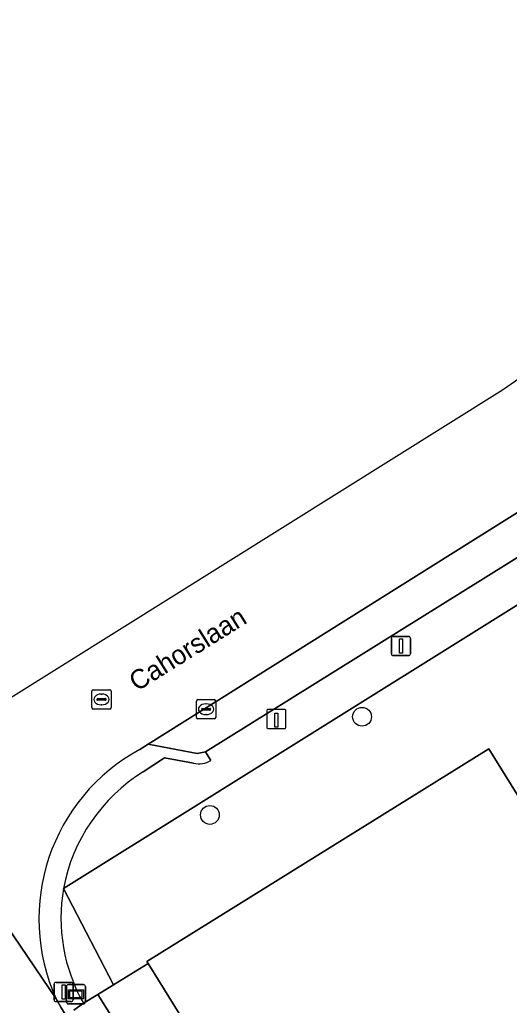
# Model space of a CAD drawing. Extents: x 158455 to 159797, y 387218 to 388672.
# Drawn here: x 158697.3 to 158722.7, y 388005.1 to 388056.4 of the extents above; entities that cross this region are included whole.
import ezdxf

# ---------------------------------------------------------------- set-up
doc = ezdxf.new("R2010")
doc.units = 0
for name, color, linetype in [('IMGEO_Boom', 7, 'Continuous'), ('IMGEO_Erf', 7, 'Continuous'), ('IMGEO_Kolk', 7, 'Continuous'), ('IMGEO_Laadpaal', 7, 'Continuous'), ('IMGEO_Lichtmast', 7, 'Continuous'), ('IMGEO_Openbare_ruimte_label', 7, 'Continuous'), ('IMGEO_Pand', 7, 'Continuous'), ('IMGEO_Parkeervlak_open', 7, 'Continuous'), ('IMGEO_Rijbaan_lokaal_gesloten', 7, 'Continuous'), ('IMGEO_Rioolput', 7, 'Continuous'), ('IMGEO_Voetpad_open', 7, 'Continuous'), ('IMGEO_Wegwijzer', 7, 'Continuous')]:
    doc.layers.add(name, color=color, linetype=linetype)

msp = doc.modelspace()

# ---------------------------------------------------------------- linework, layer by layer
at = {"layer": 'IMGEO_Boom'}
for centre in [(158715.077, 388020.119), (158707.161, 388015.014)]:
    msp.add_circle(centre, 0.489, dxfattribs=at)
at = {"layer": 'IMGEO_Erf'}
msp.add_lwpolyline([(158790.47, 387981.392), (158753.29, 388041.304), (158752.718, 388041.901), (158751.855, 388042.396), (158751.213, 388042.565), (158750.549, 388042.598), (158749.577, 388042.387), (158748.718, 388041.887), (158699.543, 388011.196), (158702.142, 388006.173), (158703.945, 388007.288), (158703.876, 388007.399), (158721.666, 388018.457), (158724.306, 388014.211), (158731.654, 388002.39)], dxfattribs=at)
at = {"layer": 'IMGEO_Kolk'}
for p, q in [((158706.459, 388020.086), (158706.459, 388020.938)), ((158706.534, 388021.012), (158707.386, 388021.012)), ((158707.46, 388020.938), (158707.46, 388020.086)), ((158706.718, 388020.506), (158706.718, 388020.518)), ((158707.156, 388020.469), (158706.758, 388020.469)), ((158706.761, 388020.555), (158707.159, 388020.555)), ((158706.947, 388020.792), (158706.972, 388020.792)), ((158707.202, 388020.518), (158707.202, 388020.506)), ((158707.386, 388020.012), (158706.534, 388020.012)), ((158706.97, 388020.232), (158706.945, 388020.232))]:
    msp.add_line(p, q, dxfattribs=at)
for points in [[(158706.459, 388020.086), (158706.459, 388020.938)], [(158706.534, 388021.012), (158707.386, 388021.012)], [(158707.46, 388020.938), (158707.46, 388020.086)], [(158707.386, 388020.012), (158706.534, 388020.012)]]:
    msp.add_lwpolyline(points, dxfattribs=at)
for centre, radius, start, end in [((158706.536, 388020.936), 0.0765, 91.552, 178.448), ((158706.536, 388020.936), 0.0765, 91.552, 178.448), ((158707.384, 388020.936), 0.0765, 1.552, 88.448), ((158707.384, 388020.936), 0.0765, 1.552, 88.448), ((158706.758, 388020.515), 0.0403, 85.8775, 175.7526), ((158706.755, 388020.505), 0.0366, 178.938, 274.7102), ((158707.159, 388020.512), 0.043, 264.8664, 352.4533), ((158707.163, 388020.517), 0.0386, 1.7309, 96.639), ((158706.536, 388020.088), 0.0765, 181.552, 268.448), ((158706.536, 388020.088), 0.0765, 181.552, 268.448), ((158707.384, 388020.088), 0.0765, 271.552, 358.448), ((158707.384, 388020.088), 0.0765, 271.552, 358.448)]:
    msp.add_arc(centre, radius, start, end, dxfattribs=at)
for centre, major_axis, ratio, start_param, end_param in [((158706.946, 388020.512), (-0.387, 0.002), 0.722429, 4.712389, 7.853982), ((158706.971, 388020.512), (-0.39, 0.002), 0.717154, 1.570796, 4.712389)]:
    msp.add_ellipse(centre, major_axis=major_axis, ratio=ratio, start_param=start_param, end_param=end_param, dxfattribs=at)
at = {"layer": 'IMGEO_Laadpaal'}
for p, q in [((158710.115, 388020.418), (158710.115, 388019.577)), ((158710.115, 388020.418), (158710.115, 388019.577)), ((158711.031, 388020.502), (158710.19, 388020.502)), ((158711.031, 388020.502), (158710.19, 388020.502)), ((158711.115, 388019.586), (158711.115, 388020.427)), ((158711.115, 388019.586), (158711.115, 388020.427)), ((158710.199, 388019.502), (158711.04, 388019.502)), ((158710.199, 388019.502), (158711.04, 388019.502))]:
    msp.add_line(p, q, dxfattribs=at)
msp.add_lwpolyline([(158710.53, 388020.315), (158710.69, 388020.315), (158710.69, 388019.582), (158710.53, 388019.582), (158710.53, 388020.315)], dxfattribs=at)
for centre, start, end in [((158710.193, 388020.424), 92.4484, 184.2845), ((158710.193, 388020.424), 92.4484, 184.2845), ((158711.037, 388020.424), 2.4484, 94.2845), ((158711.037, 388020.424), 2.4484, 94.2845), ((158710.193, 388019.58), 182.4484, 274.2845), ((158710.193, 388019.58), 182.4484, 274.2845), ((158711.037, 388019.58), 272.4484, 4.2845), ((158711.037, 388019.58), 272.4484, 4.2845)]:
    msp.add_arc(centre, 0.0779, start, end, dxfattribs=at)
at = {"layer": 'IMGEO_Lichtmast'}
for p, q in [((158716.603, 388023.398), (158716.603, 388024.198)), ((158716.603, 388024.198), (158716.603, 388023.398)), ((158716.703, 388024.298), (158717.493, 388024.298)), ((158717.493, 388024.298), (158716.703, 388024.298)), ((158717.593, 388024.198), (158717.593, 388023.398)), ((158717.593, 388023.398), (158717.593, 388024.198)), ((158717.493, 388023.298), (158716.703, 388023.298)), ((158716.703, 388023.298), (158717.493, 388023.298)), ((158699.053, 388005.405), (158699.053, 388006.205)), ((158699.053, 388006.205), (158699.053, 388005.405)), ((158699.153, 388006.305), (158699.943, 388006.305)), ((158699.943, 388006.305), (158699.153, 388006.305)), ((158700.043, 388006.205), (158700.043, 388005.405)), ((158700.043, 388005.405), (158700.043, 388006.205)), ((158699.943, 388005.305), (158699.153, 388005.305)), ((158699.153, 388005.305), (158699.943, 388005.305))]:
    msp.add_line(p, q, dxfattribs=at)
for points in [[(158717.023, 388024.173), (158717.173, 388024.173), (158717.173, 388023.423), (158717.023, 388023.423), (158717.023, 388024.173)], [(158699.473, 388006.18), (158699.623, 388006.18), (158699.623, 388005.43), (158699.473, 388005.43), (158699.473, 388006.18)]]:
    msp.add_lwpolyline(points, dxfattribs=at)
for centre, start, end in [((158716.703, 388024.198), 90, 180), ((158716.703, 388024.198), 90, 180), ((158717.493, 388024.198), 0, 90), ((158717.493, 388024.198), 360, 90), ((158716.703, 388023.398), 180, 270), ((158716.703, 388023.398), 180, 270), ((158717.493, 388023.398), 270, 0), ((158717.493, 388023.398), 270, 0), ((158699.153, 388006.205), 90, 180), ((158699.153, 388006.205), 90, 180), ((158699.943, 388006.205), 0, 90), ((158699.943, 388006.205), 360, 90), ((158699.153, 388005.405), 180, 270), ((158699.153, 388005.405), 180, 270), ((158699.943, 388005.405), 270, 0), ((158699.943, 388005.405), 270, 0)]:
    msp.add_arc(centre, 0.1, start, end, dxfattribs=at)
at = {"layer": 'IMGEO_Pand'}
msp.add_lwpolyline([(158703.876, 388007.399), (158703.945, 388007.288), (158706.413, 388003.317), (158708.475, 388000), (158711.147, 387995.701), (158715.986, 387987.917), (158721.39, 387979.223), (158725.756, 387972.2), (158728.643, 387967.556), (158732.89, 387970.196), (158743.067, 387976.522), (158728.473, 388000), (158728.288, 388000.298), (158731.654, 388002.39), (158724.306, 388014.211), (158721.666, 388018.457)], close=True, dxfattribs=at)
at = {"layer": 'IMGEO_Parkeervlak_open'}
msp.add_lwpolyline([(158742.388, 388039.817), (158743.581, 388042.372), (158738.848, 388040.074), (158733.166, 388036.841), (158727.312, 388033.343), (158703.955, 388018.697), (158706.489, 388018.215), (158706.932, 388018.293), (158728.28, 388031.59)], dxfattribs=at)
at = {"layer": 'IMGEO_Rijbaan_lokaal_gesloten'}
for points in [[(158750.198, 388056.37), (158722.39, 388037.107), (158690.997, 388017.476), (158699.164, 388005.446)], [(158703.521, 388018.425), (158703.955, 388018.697), (158727.312, 388033.343), (158733.166, 388036.841), (158738.848, 388040.074), (158743.581, 388042.372), (158743.991, 388042.57), (158746.463, 388043.958), (158747.806, 388044.596)], [(158752.139, 387920.533), (158744.044, 387933.465), (158737.513, 387943.899), (158735.552, 387947.084), (158732.398, 387952.094), (158729.154, 387957.3), (158721.495, 387969.575), (158717.131, 387976.644), (158711.737, 387985.247), (158706.858, 387993.094), (158702.152, 388000.597), (158699.396, 388005.012), (158699.164, 388005.446), (158690.997, 388017.476), (158685.259, 388013.888)]]:
    msp.add_lwpolyline(points, dxfattribs=at)
msp.add_arc((158708.298, 388009.601), 10.034, 118.4264, 204.4602, dxfattribs=at)
at = {"layer": 'IMGEO_Rioolput'}
for p, q in [((158701.019, 388020.593), (158701.019, 388021.445)), ((158701.094, 388021.519), (158701.946, 388021.519)), ((158702.02, 388021.445), (158702.02, 388020.593)), ((158701.278, 388021.013), (158701.278, 388021.025)), ((158701.716, 388020.976), (158701.318, 388020.976)), ((158701.321, 388021.062), (158701.719, 388021.062)), ((158701.507, 388021.299), (158701.532, 388021.299)), ((158701.762, 388021.025), (158701.762, 388021.013)), ((158701.946, 388020.519), (158701.094, 388020.519)), ((158701.53, 388020.739), (158701.505, 388020.739))]:
    msp.add_line(p, q, dxfattribs=at)
for points in [[(158701.019, 388020.593), (158701.019, 388021.445)], [(158701.094, 388021.519), (158701.946, 388021.519)], [(158702.02, 388021.445), (158702.02, 388020.593)], [(158701.946, 388020.519), (158701.094, 388020.519)]]:
    msp.add_lwpolyline(points, dxfattribs=at)
for centre, radius, start, end in [((158701.096, 388021.443), 0.0765, 91.552, 178.448), ((158701.096, 388021.443), 0.0765, 91.552, 178.448), ((158701.944, 388021.443), 0.0765, 1.552, 88.448), ((158701.944, 388021.443), 0.0765, 1.552, 88.448), ((158701.318, 388021.022), 0.0403, 85.8775, 175.7526), ((158701.315, 388021.012), 0.0366, 178.938, 274.7102), ((158701.719, 388021.019), 0.043, 264.8664, 352.4533), ((158701.723, 388021.024), 0.0386, 1.7309, 96.639), ((158701.096, 388020.595), 0.0765, 181.552, 268.448), ((158701.096, 388020.595), 0.0765, 181.552, 268.448), ((158701.944, 388020.595), 0.0765, 271.552, 358.448), ((158701.944, 388020.595), 0.0765, 271.552, 358.448)]:
    msp.add_arc(centre, radius, start, end, dxfattribs=at)
for centre, major_axis, ratio, start_param, end_param in [((158701.506, 388021.019), (-0.387, 0.002), 0.722429, 4.712389, 7.853982), ((158701.531, 388021.019), (-0.39, 0.002), 0.717154, 1.570796, 4.712389)]:
    msp.add_ellipse(centre, major_axis=major_axis, ratio=ratio, start_param=start_param, end_param=end_param, dxfattribs=at)
at = {"layer": 'IMGEO_Voetpad_open'}
for points in [[(158699.543, 388011.196), (158748.718, 388041.887), (158749.577, 388042.387)], [(158742.063, 388039.461), (158738.069, 388037.348), (158728.28, 388031.59), (158706.932, 388018.293), (158707.215, 388017.841)], [(158707.215, 388017.841), (158706.932, 388018.293), (158706.489, 388018.215), (158703.955, 388018.697), (158703.521, 388018.425)], [(158706.313, 388017.709), (158704.799, 388017.985), (158703.688, 388017.258)], [(158703.688, 388017.258), (158704.799, 388017.985), (158706.313, 388017.709)], [(158700.583, 388005.217), (158701.329, 388005.67), (158702.142, 388006.173), (158699.543, 388011.196)], [(158699.396, 388005.012), (158702.152, 388000.597), (158703.838, 388001.666), (158701.329, 388005.67), (158700.583, 388005.217), (158700.073, 388004.867)], [(158699.164, 388005.446), (158699.396, 388005.012)], [(158700.073, 388004.867), (158700.583, 388005.217)]]:
    msp.add_lwpolyline(points, dxfattribs=at)
msp.add_lwpolyline([(158702.142, 388006.173), (158701.329, 388005.67), (158703.838, 388001.666), (158706.413, 388003.317), (158703.945, 388007.288)], close=True, dxfattribs=at)
for centre, radius, start, end in [((158708.298, 388009.601), 10.034, 118.4264, 204.4602), ((158706.603, 388018.873), 1.2, 256, 300.6513), ((158706.603, 388018.873), 1.2, 256, 300.6513), ((158708.502, 388009.518), 9.114, 121.8799, 169.394), ((158708.502, 388009.518), 9.114, 121.8799, 169.394), ((158708.363, 388009.65), 8.955, 170.06, 209.6748), ((158708.363, 388009.65), 8.955, 170.06, 209.6748)]:
    msp.add_arc(centre, radius, start, end, dxfattribs=at)
at = {"layer": 'IMGEO_Wegwijzer'}
for p, q in [((158699.696, 388005.289), (158699.696, 388006.089)), ((158699.696, 388006.089), (158699.696, 388005.289)), ((158699.796, 388006.189), (158700.586, 388006.189)), ((158700.586, 388006.189), (158699.796, 388006.189)), ((158700.686, 388006.089), (158700.686, 388005.289)), ((158700.686, 388005.289), (158700.686, 388006.089)), ((158700.586, 388005.189), (158699.796, 388005.189)), ((158699.796, 388005.189), (158700.586, 388005.189))]:
    msp.add_line(p, q, dxfattribs=at)
for points in [[(158699.797, 388005.921), (158700.585, 388005.921), (158700.585, 388005.457), (158699.797, 388005.457), (158699.797, 388005.921)], [(158699.862, 388005.856), (158699.862, 388005.522), (158700.52, 388005.522), (158700.52, 388005.856), (158699.862, 388005.856)]]:
    msp.add_lwpolyline(points, dxfattribs=at)
for centre, start, end in [((158699.796, 388006.089), 90, 180), ((158699.796, 388006.089), 90, 180), ((158700.586, 388006.089), 0, 90), ((158700.586, 388006.089), 360, 90), ((158699.796, 388005.289), 180, 270), ((158699.796, 388005.289), 180, 270), ((158700.586, 388005.289), 270, 0), ((158700.586, 388005.289), 270, 0)]:
    msp.add_arc(centre, 0.1, start, end, dxfattribs=at)

# ---------------------------------------------------------------- texts
at = {"layer": 'IMGEO_Openbare_ruimte_label'}
msp.add_text('Cahorslaan', height=1, rotation=31.9265, dxfattribs=at).set_placement((158703.359, 388021.413))

doc.saveas('drawing.dxf')
